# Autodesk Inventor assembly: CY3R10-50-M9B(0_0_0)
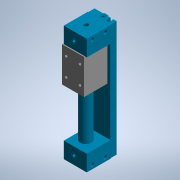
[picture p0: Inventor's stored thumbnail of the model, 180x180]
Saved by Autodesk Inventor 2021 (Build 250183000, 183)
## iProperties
Category: PARTsolutions
Company: SMC
Part Number: CY3R10-50-M9B(0_0_0)
Catalog Web Link: www.cadenas.de
Description: CY3R-Magnetically Coupled Rodless Cylinder Direct Mount Type
Vendor: SMC
Document SubType Name: Assembly
Designer: partserver
Manufacturer: SMC
Mass: 70.5141 g
Surface Area: 261.566 cm^2
Volume: 70.5141 cm^3
Density: 1 g/cm^3
PSOL_IDENT_0: {$CADENAS_DATA\23d-libs\smc_jp\actuator\rodless_cylinders\cy3\cy3r_asmtab.prj},266 {VTYP=3D},{STYP=A
PSOL_IDENT_1: SSTAB},{NB=CY3R10-50-M9B(0_0_0)},{LINA=CY3R10-50-M9B},{NN=CY3R},{DATE=12.02.2021 08:48:25},{GEOMDATE=
PSOL_IDENT_2: 14.07.2020 03:32:41},{VERSION=},{LINEID=20},{WBVAR=PIPING,THREAD1,STROKE,POS,STOP,RAIL,AUTOSWITCH,LE
PSOL_IDENT_3: AD,NUMBER,OMSC,THREAD2},{WBNUMERIC=STROKE,POS}  {NB=CY3R10-50-M9B(0_0_0)},{LINA=CY3R10-50-M9B},{KT=D
PSOL_IDENT_4: UMMY},{PIPING=},{PIPINGX='','(-) Standard type','G','(G) Centralized piping type'},{DI=1},{BORE=10},
PSOL_IDENT_5: {THREAD1=},{THREAD1X='','(-) M thread'},{STROKE=50},{STROKEX=50,100,150,200,250,300},{STDSTROKE=50,1
PSOL_IDENT_6: 00,150,200,250,300},{POS=0},{STOP=0},{COM=-},{RAIL=},{RALLX='', '(-) With switch rail', 'N', '(N) Wi
PSOL_IDENT_7: thout switch rail'},{AUTOSWITCH=-M9B},{AUTOSWITCHX='','(-) Without autoswitch (Built-in magnet)','-A
PSOL_IDENT_8: 90','A90','-A93','A93','-A96','A96','-M9N','M9N','-M9P','M9P','-M9B','M9B','-M9NW','M9NW','-M9PW','M
PSOL_IDENT_9: 9PW','-M9BW','M9BW','-M9NA','M9NA','-M9PA','M9PA','-M9BA','M9BA'},{LEAD=},{LEADX='','(-) 0.5 m','M','
PSOL_IDENT_10: (M) 1 m','L','(L) 3 m','Z','(Z) 5 m'},{NUMBER=},{NUMBERX='','(-) 2 Pcs','S','(S) 1 Pcs'},{OMSC=},{OM
PSOL_IDENT_11: SCX= '','(-) None','-XC57','(XC57) With floating joint'},{THREAD2=0},{SMIN1=25},{SMIN2=50},{SMAX1=50
PSOL_IDENT_12: 0},{SMAX2=500},{ORDER=CY3R10-50-M9B},{A=9.0},{B=6.5},{C=3.2},{CB=2},{CR=0.5},{D=12.0},{F=6.5},{G=4.0
PSOL_IDENT_13: },{GP=27},{GW=25.5},{H=26},{HA=24},{HB=14.0},{HC=25},{HP=14.0},{HP1=14.0},{HP2=0.0},{HR=24},{HS=5.0}
PSOL_IDENT_14: ,{HT=14.0},{HT1=14.0},{HT2=0.0},{JXE=M4x0.7x6},{K=9},{L=38},{LD=3.5},{M=4.0},{MM=M3x0.5},{N=4.5},{PW=
PSOL_IDENT_15: 26},{Q=68},{QW=14},{T=17.5},{TC=14.0},{W=20},{WP=13.0},{WS=8},{X=15},{Y=39.5},{Z=76},{P=M5x0.8},{PTN=
PSOL_IDENT_16: -},{PTF=-},{PPATH=cy3r/assembly/cy3r_asmsbl.prj},{MODEL=CY3R10-50-M9B},{NENN=CY3R10}
NB: CY3R10-50-M9B(0_0_0)
NN: CY3R
NT: Magnetically Coupled Rodless Cylinder Direct Mount Type
NBSYN: $ORDER.($POS._$STOP._$THREAD2.)
LINA: CY3R10-50-M9B
CATALOG: SMC (JP
ROWDESC: CY3R10
PIPING: (-) Standard type
BORE: 10
THREAD1: (-) M thread
STROKE: 50
POS: 0
STOP: Standard stroke
COM: -
RAIL: (-) With switch rail
AUTOSWITCH: M9B Solid state-General-Grommet-Indicator light:Yes-2 wire-In line
LEAD: (-) 0.5 m
NUMBER: (-) 2 Pcs
OMSC: (-) None
THREAD2: on
SUPPLIER: SMC
ARTICLENO: CY3R10-50-M9B(0_0_0)
BOMINFO: CY3R10-50-M9B
CREATOR: CADENAS GmbH
Title: CY3R10-50-M9B
Author: Cadenas PARTsolutions
Comments: Magnetically Coupled Rodless Cylinder Direct Mount Type
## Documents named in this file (4)
- D:\01 Paralaia\Grupos de Traballo\GT Maquetas\CAD 3D\E_Medida\CY3R10-50-M9B\CY3R10-50-M9B(0_0_0).iam
- D:\01 Paralaia\Grupos de Traballo\GT Maquetas\CAD 3D\E_Medida\CY3R10-50-M9B\CY3R10-50-M9B(0)_CT.ipt
- D:\01 Paralaia\Grupos de Traballo\GT Maquetas\CAD 3D\E_Medida\CY3R10-50-M9B\CY3R10(0)_BODY.ipt
- D:\01 Paralaia\Grupos de Traballo\GT Maquetas\CAD 3D\E_Medida\CY3R10-50-M9B\CY3R-M9B_SW.ipt
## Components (4 placed, 3 different names)
1. CY3R10-50-M9B(0)_CT:1 — Insertar:1, Ángulo:1, Insertar:2
2. CY3R10(0)_BODY:1 — Insertar:1, Ángulo:1, Insertar:2
3. CY3R-M9B_SW:1
4. CY3R-M9B_SW:2
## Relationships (3: Insert 2, Angle 1)
- Insertar:1: CY3R10-50-M9B(0)_CT:1 ↔ CY3R10(0)_BODY:1
- Ángulo:1 [Angle]: CY3R10-50-M9B(0)_CT:1 ↔ CY3R10(0)_BODY:1
- Insertar:2: CY3R10-50-M9B(0)_CT:1 ↔ CY3R10(0)_BODY:1
